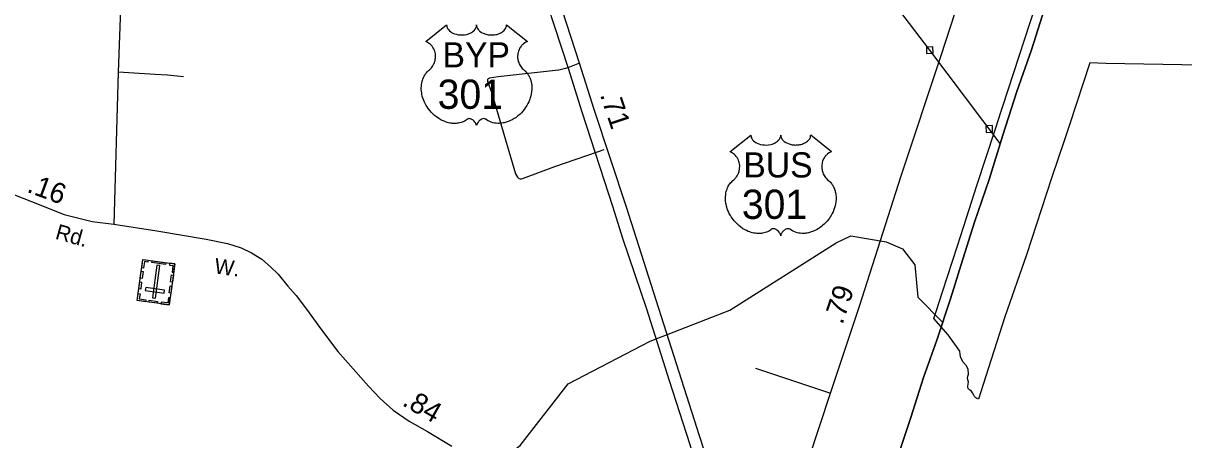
# Model space of a CAD drawing. Extents: x 2220236 to 2384410, y 720751 to 894131.
# Drawn here: x 2344862 to 2351999, y 780671 to 783236 of the extents above; entities that cross this region are included whole.
import ezdxf

# ---------------------------------------------------------------- set-up
doc = ezdxf.new("R2010")
doc.units = 0
for name, color, linetype in [('Exist Boundary Political City Limit New', 7, 'Continuous'), ('Exist Boundary Political CountyLine', 7, 'Continuous'), ('Exist Cultural Cemetery CELL', 7, 'Continuous'), ('Exist Hydrographic Misc Water Feature', 7, 'Continuous'), ('Exist Railroad Mainline', 7, 'Continuous'), ('Exist Road Non-System Type 51', 7, 'Continuous'), ('Exist Road Primary US Attributed', 7, 'Continuous'), ('Exist Road Primary US Divided Attributed', 7, 'Continuous'), ('Exist Road Primary US Mileage Hundredths English Label', 7, 'Continuous'), ('Exist Road Primary US Shield CELL', 7, 'Continuous'), ('Exist Road Primary US Shield Number Label', 7, 'Continuous'), ('Exist Road Secondary Mileage Hundredths English Label', 7, 'Continuous'), ('Exist Road Secondary Type 51 Attributed', 7, 'Continuous'), ('Exist Road Secondary Type 51 Label', 7, 'Continuous'), ('Exist Utilities Electrical Transmission Line', 7, 'Continuous'), ('Map Preparation Boundary City Limit Buffer Line', 7, 'Continuous')]:
    doc.layers.add(name, color=color, linetype=linetype)

msp = doc.modelspace()

# ---------------------------------------------------------------- linework, layer by layer
at = {"layer": 'Exist Boundary Political City Limit New'}
msp.add_lwpolyline([(2352385.2, 782970.6), (2351987.8, 782979.4), (2351518.5, 782988.2), (2351420.8, 782991.4), (2351296.2, 782609.5), (2351265.8, 782517.7), (2351185.5, 782282.3), (2351030.8, 781810.3), (2350899, 781428.3), (2350764.2, 781012.3), (2350735.8, 780921.9), (2350726.2, 780926.4), (2350719.8, 780930.8), (2350712.8, 780937.7), (2350707, 780946.3), (2350699.8, 780960), (2350692.8, 780969.9), (2350683.5, 780977.2), (2350673.5, 780988.3), (2350670.8, 780995.2), (2350670.8, 781002.3), (2350675, 781025.9), (2350669, 781049.5), (2350670.8, 781062.6), (2350674.2, 781074.8), (2350673.2, 781105.6), (2350660.2, 781129.1), (2350642.5, 781149.1), (2350628.2, 781177.1), (2350622.8, 781197.4), (2350620.8, 781216.8), (2350550.8, 781317.9), (2350461.5, 781418), (2350475.8, 781462.3), (2350514.5, 781581.7), (2350606.8, 781865.9), (2350663, 782038.9), (2350727.2, 782236.4), (2350838.5, 782579), (2350850.8, 782617.1), (2350851.2, 782618.4), (2351157, 783556.1)], dxfattribs=at)
at = {"layer": 'Exist Boundary Political CountyLine'}
msp.add_lwpolyline([(2352041.4, 786067.5), (2351966.4, 785827.1), (2351845.8, 785446.1), (2351756.6, 785180.1), (2351656.9, 784880.8), (2351572.4, 784619.5), (2351484.1, 784371.5), (2351391, 784099.8), (2351335, 783914.5), (2351238.2, 783633.3), (2351155.6, 783362.5), (2351061.6, 783072.7), (2350972.3, 782816.2), (2350885.9, 782547.3), (2350801.4, 782274.6), (2350712.2, 782010.5), (2350641, 781783.4), (2350565, 781540.2), (2350480.5, 781284.6), (2350398.9, 781054.7), (2350320, 780808.6), (2350222.3, 780513.1)], dxfattribs=at)
at = {"layer": 'Exist Cultural Cemetery CELL'}
for points in [[(2345760.5, 781501.6), (2345563.3, 781528.9), (2345598.1, 781781.1), (2345795.3, 781753.9)], [(2345630.9, 781776.6), (2345629.4, 781765.2), (2345607.6, 781768.2), (2345602.1, 781728.2), (2345591, 781729.7), (2345598.1, 781781.1)], [(2345736.9, 781750.3), (2345652.8, 781762), (2345654.4, 781773.2), (2345738.4, 781761.6)], [(2345762.6, 781758.3), (2345761, 781747), (2345782.8, 781743.9), (2345777.3, 781703.9), (2345788.3, 781702.4), (2345795.4, 781753.8)], [(2345599.5, 781707.9), (2345593.6, 781665), (2345582.3, 781666.6), (2345588.2, 781709.5)], [(2345656.5, 781545.6), (2345675, 781543), (2345702.8, 781743.9), (2345684.3, 781746.4)], [(2345785.8, 781684.6), (2345779.9, 781641.7), (2345768.6, 781643.2), (2345774.5, 781686.1)], [(2345590.5, 781642.6), (2345584.5, 781599.7), (2345573.3, 781601.3), (2345579.2, 781644.2)], [(2345729.4, 781574.6), (2345732, 781593.1), (2345615.3, 781609.2), (2345612.8, 781590.7)], [(2345776.6, 781618), (2345770.7, 781575.1), (2345759.4, 781576.6), (2345765.3, 781619.5)], [(2345569.2, 781571.8), (2345580.4, 781570.3), (2345576, 781538.4), (2345616.2, 781532.8), (2345614.7, 781521.8), (2345563.2, 781528.9)], [(2345766.4, 781544.5), (2345755.2, 781546.1), (2345750.8, 781514.2), (2345710.6, 781519.8), (2345709.1, 781508.7), (2345760.5, 781501.6)], [(2345687.2, 781511.8), (2345635.8, 781518.9), (2345637.4, 781530.2), (2345688.7, 781523.1)]]:
    msp.add_lwpolyline(points, close=True, dxfattribs=at)
at = {"layer": 'Exist Hydrographic Misc Water Feature'}
msp.add_lwpolyline([(2346758.6, 779305.7), (2347256.4, 779480.3), (2347550.5, 779948.4), (2347531.4, 780184), (2347595.6, 780350.7), (2347686.4, 780459.4), (2347917.5, 780636.3), (2348212.6, 781015.9), (2348717.5, 781279.4), (2349206.5, 781470), (2349860.6, 781883.9), (2349951.5, 781927), (2350168.6, 781889.9), (2350268.5, 781848.1), (2350344.6, 781749.4), (2350363.6, 781550), (2350516.4, 781393.1)], dxfattribs=at)
at = {"layer": 'Exist Railroad Mainline'}
msp.add_lwpolyline([(2350222.3, 780513.1), (2350320, 780808.6), (2350398.9, 781054.7), (2350480.5, 781284.6), (2350565, 781540.2), (2350641, 781783.4), (2350712.2, 782010.5), (2350801.4, 782274.6), (2350885.9, 782547.3), (2350972.3, 782816.2), (2351061.6, 783072.7), (2351155.6, 783362.5), (2351238.2, 783633.3), (2351335, 783914.5), (2351391, 784099.8), (2351484.1, 784371.5), (2351572.4, 784619.5), (2351656.9, 784880.8), (2351756.6, 785180.1), (2351845.8, 785446.1), (2351966.4, 785827.1), (2352041.4, 786067.5)], dxfattribs=at)
at = {"layer": 'Exist Road Non-System Type 51'}
for p, q in [((2348282.9, 782989.3), (2348221.3, 782965.1)), ((2348328.8, 782421.8), (2348392.7, 782444)), ((2348392.7, 782444), (2348435.3, 782458.8)), ((2349364.6, 781112), (2349826, 780958.2))]:
    msp.add_line(p, q, dxfattribs=at)
for points in [[(2348221.3, 782965.1), (2348196.3, 782956.3), (2348156.1, 782947)], [(2345847.9, 782906.4), (2345749.7, 782915.8), (2345674.4, 782921.2), (2345447.1, 782934.6)], [(2348156.1, 782947), (2348152.8, 782946.2), (2347782, 782905.3), (2347729.8, 782897.8), (2347722.3, 782894.4), (2347717.8, 782888.8), (2347717.8, 782879.9), (2347742.7, 782811.9), (2347889.4, 782308.2), (2347901.3, 782287.3), (2347909.5, 782280.2), (2347918.5, 782277.6), (2347927.2, 782278.6), (2347938.6, 782282.9), (2348131, 782353), (2348328.8, 782421.8)]]:
    msp.add_lwpolyline(points, dxfattribs=at)
at = {"layer": 'Exist Road Primary US Attributed'}
msp.add_lwpolyline([(2349423.6, 779733.7), (2349826, 780958.2), (2350004.8, 781494.8), (2350260.7, 782295.8), (2350506.4, 783037.3), (2351081.3, 784803.5), (2351440.4, 785897.5), (2351562, 786262.8)], dxfattribs=at)
at = {"layer": 'Exist Road Primary US Divided Attributed'}
for points in [[(2347364.1, 785590.9), (2347464.9, 785273.3), (2347645.7, 784713.9), (2347836.5, 784127.9), (2348002.5, 783605.1), (2348213.2, 782959.4), (2348297.8, 782690.5), (2348488.6, 782104.6), (2348548.3, 781913.7), (2348694.3, 781477.1), (2348833.7, 781035.6), (2348961.4, 780642.2), (2349006.2, 780487.8), (2349051, 780335.1), (2349069.3, 780262.1), (2349099.2, 780077.8), (2349118.4, 779923.7), (2349131, 779784.6)], [(2349241.6, 779764.7), (2349236, 779845.5), (2349225, 779918.5), (2349206.2, 780010.3), (2349182.1, 780140.9), (2349148.9, 780288.6), (2349077.6, 780519.4), (2349021.2, 780695.3), (2348896.7, 781088.7), (2348770.6, 781480.4), (2348571.5, 782102.9), (2348372.5, 782703.8), (2348282.9, 782989.3), (2348072.1, 783641.6), (2347906.2, 784151.2), (2347723.7, 784730.5), (2347601, 785102.3), (2347504.7, 785391.1), (2347439.5, 785590.9)]]:
    msp.add_lwpolyline(points, dxfattribs=at)
at = {"layer": 'Exist Road Primary US Shield CELL'}
for points in [[(2347466, 783225.1), (2347466.4, 783219.7), (2347467.6, 783213.4), (2347468.6, 783210.2), (2347471.6, 783203.9), (2347476.5, 783196.6), (2347483.2, 783189.3), (2347490.9, 783183), (2347496.1, 783179.7), (2347504.9, 783175), (2347514.8, 783170.8), (2347525.9, 783167.6), (2347537.2, 783165.3), (2347549.6, 783164), (2347561.8, 783163.7), (2347575, 783164.7), (2347589.6, 783167.5), (2347596.4, 783169.3), (2347603.9, 783171.9), (2347610.9, 783174.8), (2347618.6, 783178.9), (2347624.7, 783182.8), (2347629.5, 783186.3), (2347636.4, 783192.8), (2347641.8, 783199.6), (2347644.1, 783203.4), (2347646, 783207), (2347648.7, 783214.8), (2347649.5, 783218.2), (2347650, 783225.3), (2347650.5, 783219.4), (2347651.1, 783215.6), (2347652.1, 783212), (2347653.6, 783208.1), (2347656.3, 783202.6), (2347659.4, 783198.1), (2347665.1, 783191.3), (2347668.7, 783188), (2347671.9, 783185.3), (2347680.7, 783179.3), (2347690.9, 783174.1), (2347695.9, 783171.9), (2347701.1, 783170.1), (2347707.6, 783168.1), (2347714.4, 783166.5), (2347721, 783165.4), (2347727.9, 783164.4), (2347734.9, 783163.9), (2347740.6, 783163.7), (2347747.5, 783163.8), (2347754, 783164.2), (2347760.6, 783165), (2347767.9, 783166.2), (2347773.8, 783167.5), (2347781.5, 783169.5), (2347788.5, 783172), (2347794.6, 783174.7), (2347802.6, 783178.9), (2347809.1, 783182.9), (2347813.8, 783186.7), (2347819.4, 783191.9), (2347824.7, 783198), (2347827.8, 783202.5), (2347830, 783207.1), (2347832.1, 783212), (2347833.3, 783217.2), (2347833.9, 783221.6), (2347834.1, 783225.5), (2347962.7, 783123), (2347959.6, 783121.9), (2347952.6, 783118.4), (2347947.1, 783115.2), (2347938.3, 783108.9), (2347934.5, 783105.5), (2347930.7, 783102), (2347927.2, 783098.2), (2347924.1, 783094.6), (2347920.4, 783089.4), (2347917, 783084.3), (2347913.8, 783078.6), (2347911.4, 783073.6), (2347907.4, 783063.3), (2347905.5, 783056.7), (2347904.3, 783051.2), (2347902.8, 783039.7), (2347902.4, 783034.3), (2347902.4, 783028.9), (2347902.7, 783023.2), (2347903.2, 783017.7), (2347904.2, 783012), (2347905.1, 783007), (2347906.7, 783000.8), (2347909, 782993.7), (2347911.8, 782986.8), (2347917.7, 782975.6), (2347925.3, 782964.2), (2347930.7, 782957.8), (2347936, 782952.3), (2347943.9, 782945.7), (2347948.2, 782941.9), (2347953.1, 782936.9), (2347961.2, 782927.6), (2347964.5, 782923.2), (2347967.8, 782918.2), (2347970.8, 782913.1), (2347973.8, 782907.7), (2347976.3, 782902.9), (2347980.8, 782891.9), (2347984.1, 782881.1), (2347985.6, 782875.5), (2347988, 782862.9), (2347988.9, 782856.7), (2347989.9, 782844.4), (2347989.9, 782829.5), (2347988.8, 782815.3), (2347986.1, 782798.8), (2347983.9, 782789), (2347980.6, 782777.5), (2347977.3, 782767.5), (2347971.4, 782752.9), (2347966.2, 782742.2), (2347959.4, 782729.8), (2347954.8, 782722.3), (2347949.4, 782714.2), (2347942.7, 782704.9), (2347934.8, 782695), (2347925.3, 782684.6), (2347917.6, 782677), (2347907.6, 782668), (2347901.5, 782663), (2347892.8, 782656.4), (2347881, 782648.5), (2347869.3, 782641.8), (2347859.3, 782636.7), (2347850.5, 782632.9), (2347839.1, 782628.6), (2347820.2, 782623.3), (2347813.2, 782621.9), (2347805, 782620.7), (2347797.4, 782619.9), (2347789.9, 782619.4), (2347779.9, 782619.4), (2347770, 782620.2), (2347760.5, 782621.6), (2347750.7, 782623.6), (2347740.5, 782626.7), (2347731.2, 782630.3), (2347721.8, 782634.9), (2347705.9, 782645), (2347701.3, 782647.4), (2347698.7, 782648.1), (2347692.5, 782648.4), (2347686.8, 782647.2), (2347680.8, 782644.8), (2347677.3, 782642.9), (2347672.5, 782639.8), (2347668.9, 782636.9), (2347664.5, 782632.7), (2347661.4, 782629.2), (2347659.1, 782626.5), (2347654.6, 782619.4), (2347653, 782616.1), (2347651.4, 782611.8), (2347649.9, 782605.4), (2347647.9, 782613.4), (2347645.5, 782618.8), (2347642.8, 782623.3), (2347639.9, 782627.3), (2347635.5, 782632.5), (2347631.4, 782636.4), (2347626.6, 782640.3), (2347621.4, 782643.5), (2347617.3, 782645.6), (2347613.5, 782647), (2347608.8, 782648.2), (2347605, 782648.5), (2347601.9, 782648.4), (2347597.6, 782647.4), (2347591.8, 782643.2), (2347586.3, 782639.4), (2347580.3, 782635.7), (2347573.2, 782631.9), (2347567.9, 782629.5), (2347561.7, 782627), (2347554.4, 782624.6), (2347546.5, 782622.6), (2347538.4, 782621), (2347531.3, 782619.8), (2347523.6, 782619.1), (2347516.7, 782618.9), (2347509.5, 782619), (2347502.7, 782619.5), (2347494.9, 782620.2), (2347485.2, 782621.6), (2347477.1, 782623.5), (2347468.6, 782625.7), (2347459.9, 782628.5), (2347450.5, 782632.1), (2347438.8, 782637.1), (2347430.7, 782641.3), (2347417.9, 782648.7), (2347402.8, 782659.1), (2347391.5, 782668.3), (2347383.2, 782675.8), (2347370.9, 782688.3), (2347363.8, 782696.4), (2347352.5, 782711), (2347345.3, 782721.6), (2347340.6, 782729.3), (2347333.8, 782741.8), (2347330, 782749.6), (2347325.1, 782761), (2347321.3, 782771.4), (2347318.1, 782781.3), (2347316.4, 782787.6), (2347314, 782798.6), (2347312.5, 782806.4), (2347311, 782817.2), (2347310.2, 782828.5), (2347310.1, 782838.9), (2347310.4, 782847.6), (2347311.4, 782857.7), (2347313.1, 782868.4), (2347315.1, 782877.6), (2347317, 782884.2), (2347319.7, 782892.2), (2347323.3, 782901.1), (2347327.6, 782909.6), (2347331.6, 782916.7), (2347336.7, 782924.3), (2347341.7, 782930.8), (2347348.3, 782937.9), (2347355.1, 782944.4), (2347361.4, 782949.5), (2347368.8, 782956.8), (2347372.7, 782961.2), (2347377.4, 782967.4), (2347381.1, 782973.1), (2347384.1, 782978.2), (2347388, 782985.7), (2347390.3, 782991.3), (2347393.3, 783000), (2347394.8, 783006.1), (2347396.3, 783013.9), (2347397.3, 783021.3), (2347397.7, 783030.5), (2347397.4, 783038.1), (2347396.5, 783046.9), (2347394.8, 783055.5), (2347392.8, 783062.9), (2347389.6, 783071.4), (2347386.7, 783077.6), (2347381.7, 783086.1), (2347376.2, 783093.9), (2347370.6, 783100.3), (2347364.9, 783106), (2347359.4, 783110.2), (2347354.2, 783114), (2347347.7, 783117.9), (2347341.4, 783121), (2347337.4, 783122.6)], [(2349336.5, 782547.6), (2349336.8, 782542.3), (2349338.1, 782535.9), (2349339.1, 782532.7), (2349342.1, 782526.4), (2349346.9, 782519.1), (2349353.7, 782511.9), (2349361.4, 782505.5), (2349366.5, 782502.2), (2349375.3, 782497.5), (2349385.3, 782493.3), (2349396.4, 782490.1), (2349407.7, 782487.8), (2349420, 782486.5), (2349432.3, 782486.2), (2349445.5, 782487.2), (2349460.1, 782490), (2349466.8, 782491.8), (2349474.4, 782494.4), (2349481.3, 782497.3), (2349489, 782501.4), (2349495.2, 782505.3), (2349500, 782508.8), (2349506.8, 782515.4), (2349512.3, 782522.1), (2349514.5, 782525.9), (2349516.5, 782529.6), (2349519.2, 782537.3), (2349520, 782540.7), (2349520.5, 782547.8), (2349520.9, 782541.9), (2349521.6, 782538.1), (2349522.5, 782534.5), (2349524.1, 782530.6), (2349526.8, 782525.2), (2349529.8, 782520.6), (2349535.6, 782513.8), (2349539.1, 782510.5), (2349542.4, 782507.8), (2349551.1, 782501.8), (2349561.4, 782496.7), (2349566.4, 782494.5), (2349571.5, 782492.6), (2349578.1, 782490.7), (2349584.8, 782489.1), (2349591.5, 782487.9), (2349598.3, 782486.9), (2349605.3, 782486.4), (2349611, 782486.2), (2349618, 782486.3), (2349624.5, 782486.7), (2349631.1, 782487.5), (2349638.4, 782488.7), (2349644.2, 782490), (2349652, 782492), (2349658.9, 782494.5), (2349665.1, 782497.2), (2349673.1, 782501.4), (2349679.5, 782505.4), (2349684.2, 782509.2), (2349689.9, 782514.4), (2349695.2, 782520.5), (2349698.3, 782525), (2349700.5, 782529.6), (2349702.5, 782534.5), (2349703.8, 782539.7), (2349704.4, 782544.2), (2349704.5, 782548), (2349833.1, 782445.5), (2349830.1, 782444.4), (2349823.1, 782441), (2349817.6, 782437.7), (2349808.7, 782431.5), (2349804.9, 782428), (2349801.1, 782424.5), (2349797.6, 782420.7), (2349794.5, 782417.1), (2349790.8, 782411.9), (2349787.5, 782406.8), (2349784.2, 782401.1), (2349781.8, 782396.1), (2349777.9, 782385.8), (2349776, 782379.3), (2349774.8, 782373.7), (2349773.2, 782362.2), (2349772.9, 782356.8), (2349772.9, 782351.4), (2349773.2, 782345.7), (2349773.7, 782340.2), (2349774.7, 782334.5), (2349775.6, 782329.5), (2349777.2, 782323.3), (2349779.5, 782316.2), (2349782.3, 782309.3), (2349788.2, 782298.1), (2349795.7, 782286.7), (2349801.1, 782280.3), (2349806.4, 782274.9), (2349814.4, 782268.2), (2349818.7, 782264.4), (2349823.6, 782259.4), (2349831.6, 782250.1), (2349834.9, 782245.7), (2349838.2, 782240.7), (2349841.3, 782235.6), (2349844.3, 782230.2), (2349846.7, 782225.4), (2349851.2, 782214.4), (2349854.5, 782203.7), (2349856.1, 782198), (2349858.5, 782185.4), (2349859.4, 782179.2), (2349860.4, 782166.9), (2349860.4, 782152), (2349859.3, 782137.8), (2349856.6, 782121.4), (2349854.4, 782111.5), (2349851, 782100), (2349847.7, 782090), (2349841.9, 782075.4), (2349836.7, 782064.7), (2349829.9, 782052.3), (2349825.3, 782044.8), (2349819.9, 782036.7), (2349813.1, 782027.4), (2349805.2, 782017.6), (2349795.7, 782007.1), (2349788.1, 781999.5), (2349778, 781990.5), (2349772, 781985.5), (2349763.3, 781979), (2349751.4, 781971.1), (2349739.8, 781964.3), (2349729.8, 781959.2), (2349721, 781955.4), (2349709.6, 781951.1), (2349690.6, 781945.8), (2349683.7, 781944.4), (2349675.5, 781943.2), (2349667.8, 781942.4), (2349660.4, 781942), (2349650.4, 781942), (2349640.4, 781942.7), (2349631, 781944.1), (2349621.2, 781946.1), (2349610.9, 781949.2), (2349601.6, 781952.8), (2349592.2, 781957.5), (2349576.3, 781967.5), (2349571.7, 781969.9), (2349569.1, 781970.6), (2349563, 781970.9), (2349557.2, 781969.7), (2349551.3, 781967.3), (2349547.7, 781965.4), (2349543, 781962.3), (2349539.3, 781959.4), (2349534.9, 781955.2), (2349531.9, 781951.8), (2349529.6, 781949), (2349525.1, 781942), (2349523.5, 781938.6), (2349521.8, 781934.3), (2349520.4, 781927.9), (2349518.3, 781935.9), (2349516, 781941.3), (2349513.2, 781945.8), (2349510.4, 781949.9), (2349505.9, 781955), (2349501.9, 781958.9), (2349497, 781962.8), (2349491.9, 781966), (2349487.7, 781968.1), (2349483.9, 781969.5), (2349479.3, 781970.7), (2349475.5, 781971), (2349472.4, 781970.9), (2349468.1, 781969.9), (2349462.3, 781965.7), (2349456.8, 781961.9), (2349450.8, 781958.2), (2349443.6, 781954.4), (2349438.4, 781952), (2349432.2, 781949.6), (2349424.9, 781947.1), (2349417, 781945.1), (2349408.8, 781943.5), (2349401.7, 781942.3), (2349394, 781941.6), (2349387.1, 781941.4), (2349379.9, 781941.5), (2349373.2, 781942), (2349365.3, 781942.7), (2349355.6, 781944.2), (2349347.6, 781946), (2349339.1, 781948.3), (2349330.3, 781951), (2349321, 781954.6), (2349309.3, 781959.7), (2349301.2, 781963.8), (2349288.3, 781971.2), (2349273.3, 781981.6), (2349261.9, 781990.8), (2349253.6, 781998.3), (2349241.4, 782010.8), (2349234.2, 782018.9), (2349222.9, 782033.5), (2349215.7, 782044.1), (2349211, 782051.8), (2349204.2, 782064.3), (2349200.5, 782072.1), (2349195.6, 782083.5), (2349191.8, 782093.9), (2349188.6, 782103.8), (2349186.9, 782110.1), (2349184.4, 782121.1), (2349182.9, 782129), (2349181.5, 782139.7), (2349180.7, 782151), (2349180.6, 782161.4), (2349180.8, 782170.1), (2349181.8, 782180.2), (2349183.5, 782190.9), (2349185.6, 782200.1), (2349187.4, 782206.7), (2349190.2, 782214.7), (2349193.8, 782223.6), (2349198, 782232.1), (2349202.1, 782239.2), (2349207.2, 782246.8), (2349212.2, 782253.3), (2349218.8, 782260.4), (2349225.6, 782266.9), (2349231.9, 782272), (2349239.3, 782279.3), (2349243.2, 782283.7), (2349247.8, 782289.9), (2349251.6, 782295.6), (2349254.5, 782300.7), (2349258.4, 782308.2), (2349260.8, 782313.8), (2349263.8, 782322.5), (2349265.2, 782328.6), (2349266.8, 782336.4), (2349267.7, 782343.8), (2349268.1, 782353), (2349267.9, 782360.6), (2349266.9, 782369.5), (2349265.2, 782378), (2349263.2, 782385.4), (2349260, 782393.9), (2349257.1, 782400.2), (2349252.2, 782408.6), (2349246.7, 782416.4), (2349241, 782422.8), (2349235.4, 782428.5), (2349229.9, 782432.8), (2349224.7, 782436.5), (2349218.2, 782440.4), (2349211.8, 782443.5), (2349207.9, 782445.1)]]:
    msp.add_lwpolyline(points, close=True, dxfattribs=at)
at = {"layer": 'Exist Road Secondary Type 51 Attributed'}
for points in [[(2345718.1, 786009), (2345715.4, 785945.8), (2345673.6, 785638), (2345609.9, 785273.6), (2345562, 785046.7), (2345534.5, 784879.3), (2345504.3, 784574.4), (2345478.1, 783832.2), (2345447.1, 782934.6), (2345420.2, 781998)], [(2344623.4, 782255.7), (2344741.7, 782207.2), (2344913.8, 782138.2), (2345114.3, 782059.2), (2345286.4, 782016.1), (2345420.2, 781998)], [(2345420.2, 781998), (2345683.7, 781957.5), (2345986.9, 781907), (2346118.3, 781879.2), (2346201.7, 781852.6), (2346265.1, 781822.6), (2346330, 781782.5), (2346383.7, 781736.3), (2346430.7, 781690.5), (2346489.5, 781617.3), (2346540.1, 781559.9), (2346605.2, 781474.7), (2346689.4, 781355.8), (2346796.8, 781215.4), (2346984.7, 781001.4), (2347057.6, 780926.4), (2347136.6, 780853.4), (2347235.3, 780786.6), (2347348, 780721.9), (2347498.7, 780632)]]:
    msp.add_lwpolyline(points, dxfattribs=at)
at = {"layer": 'Exist Utilities Electrical Transmission Line'}
for points in [[(2350869.9, 782495.5), (2350436.8, 783070.4), (2350101.5, 783514.1), (2350174, 784150.7), (2350246.2, 784777.5), (2350304.8, 785395.9), (2350020.7, 786086.2), (2349800.8, 786581.5), (2349578.7, 787102.6), (2349360.6, 787617.7), (2349132.2, 788154.8)], [(2350417.6, 783049.6), (2350457.5, 783051.2), (2350455.9, 783091.1), (2350416, 783089.5), (2350417.6, 783049.6)], [(2350783.4, 782564.1), (2350823.3, 782565.7), (2350821.7, 782605.7), (2350781.7, 782604), (2350783.4, 782564.1)]]:
    msp.add_lwpolyline(points, dxfattribs=at)
at = {"layer": 'Map Preparation Boundary City Limit Buffer Line'}
msp.add_lwpolyline([(2352385.2, 782970.6), (2351987.8, 782979.4), (2351518.5, 782988.2), (2351420.8, 782991.4), (2351296.2, 782609.5), (2351265.8, 782517.7), (2351185.5, 782282.3), (2351030.8, 781810.3), (2350899, 781428.3), (2350764.2, 781012.3), (2350735.8, 780921.9), (2350726.2, 780926.4), (2350719.8, 780930.8), (2350712.8, 780937.7), (2350707, 780946.3), (2350699.8, 780960), (2350692.8, 780969.9), (2350683.5, 780977.2), (2350673.5, 780988.3), (2350670.8, 780995.2), (2350670.8, 781002.3), (2350675, 781025.9), (2350669, 781049.5), (2350670.8, 781062.6), (2350674.2, 781074.8), (2350673.2, 781105.6), (2350660.2, 781129.1), (2350642.5, 781149.1), (2350628.2, 781177.1), (2350622.8, 781197.4), (2350620.8, 781216.8), (2350550.8, 781317.9), (2350461.5, 781418), (2350475.8, 781462.3), (2350514.5, 781581.7), (2350606.8, 781865.9), (2350663, 782038.9), (2350727.2, 782236.4), (2350838.5, 782579), (2350850.8, 782617.1), (2350851.2, 782618.4), (2351157, 783556.1)], dxfattribs=at)

# ---------------------------------------------------------------- texts
at = {"layer": 'Exist Road Primary US Mileage Hundredths English Label'}
for s, rotation, p in [('.71', 288.33226, (2348407.8, 782795.8)), ('.79', 71.57601, (2349899.5, 781376.5))]:
    msp.add_text(s, height=125, rotation=rotation, dxfattribs=at).set_placement(p)
at = {"layer": 'Exist Road Primary US Shield Number Label'}
for s, height, p in [('BYP', 155, (2347440.7, 782963.7)), ('301', 180, (2347410.8, 782708.9)), ('BUS', 155, (2349290.2, 782286.3)), ('301', 180, (2349281.3, 782031.4))]:
    msp.add_text(s, height=height, dxfattribs=at).set_placement(p)
at = {"layer": 'Exist Road Secondary Mileage Hundredths English Label'}
for s, rotation, p in [('.16', 339.67712, (2344879, 782198.8)), ('.84', 330.14101, (2347186.6, 780886.7))]:
    msp.add_text(s, height=125, rotation=rotation, dxfattribs=at).set_placement(p)
at = {"layer": 'Exist Road Secondary Type 51 Label'}
for s, rotation, p in [('Rd.', 344.36813, (2345054, 781910)), ('W.', 352.14235, (2346033.4, 781696.4))]:
    msp.add_text(s, height=95, rotation=rotation, dxfattribs=at).set_placement(p)

doc.saveas('drawing.dxf')
